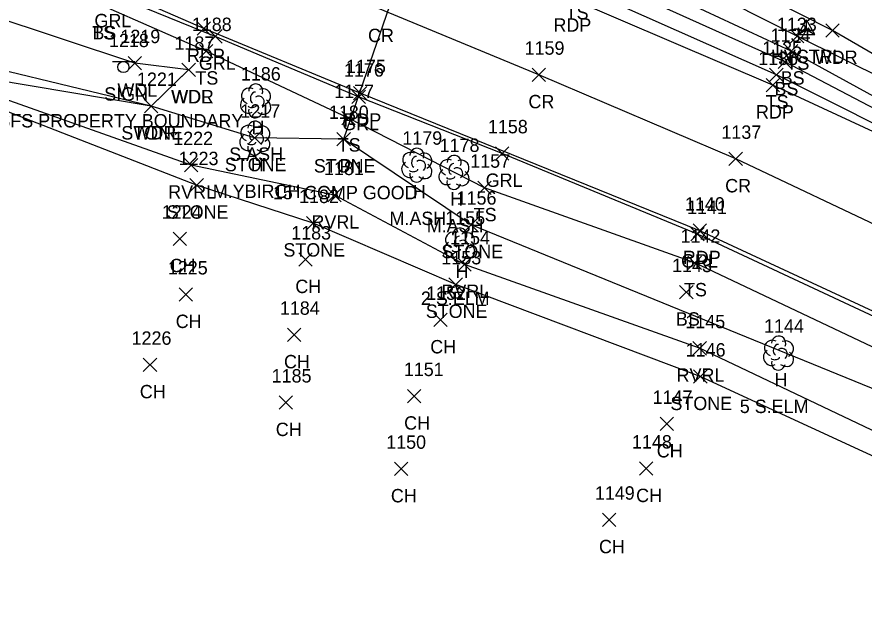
# Model space of a CAD drawing. Extents: x 1499292 to 1501024, y 534584 to 538043.
# Drawn here: x 1499970.1 to 1500096.6, y 537400.3 to 537488 of the extents above; entities that cross this region are included whole.
import ezdxf

# ---------------------------------------------------------------- set-up
doc = ezdxf.new("R2010")
doc.units = 0
for name, color, linetype in [('C_A', 7, 'Continuous'), ('CPSM', 7, 'Continuous'), ('D_A', 7, 'Continuous'), ('D_C', 7, 'Continuous'), ('D_I', 7, 'Continuous'), ('D_TIC', 7, 'Continuous'), ('DCP', 7, 'Continuous'), ('L_A', 7, 'Continuous'), ('L_C', 7, 'Continuous'), ('L_I', 7, 'Continuous'), ('L_TIC', 7, 'Continuous'), ('LASF', 7, 'Continuous'), ('LAWA', 7, 'Continuous'), ('LAWE', 7, 'Continuous'), ('LELB', 7, 'Continuous'), ('LTD', 7, 'Continuous'), ('P_A', 7, 'Continuous'), ('P_I', 7, 'Continuous'), ('P_TIC', 7, 'Continuous'), ('PET', 7, 'Continuous'), ('PRC', 7, 'Continuous'), ('R_A', 7, 'Continuous'), ('R_I', 7, 'Continuous'), ('R_TIC', 7, 'Continuous'), ('RGR', 7, 'Continuous'), ('S_A', 7, 'Continuous'), ('S_C', 7, 'Continuous'), ('S_I', 7, 'Continuous'), ('SSGN', 7, 'Continuous')]:
    doc.layers.add(name, color=color, linetype=linetype)

msp = doc.modelspace()

# ---------------------------------------------------------------- linework, layer by layer
at = {"layer": 'CPSM'}
for p, q in [((1500086.72, 537485.43), (1500087.97, 537487.6)), ((1500089.22, 537485.43), (1500087.97, 537487.6)), ((1500087.97, 537486.15), (1500087.97, 537487.6)), ((1500086.72, 537485.43), (1500087.97, 537486.15)), ((1500087.97, 537486.15), (1500087.97, 537486.15)), ((1500087.97, 537486.15), (1500089.22, 537485.43)), ((1500086.72, 537485.43), (1500089.22, 537485.43))]:
    msp.add_line(p, q, dxfattribs=at)
at = {"layer": 'D_TIC'}
for points in [[(1500017.89, 537468.8), (1500019.89, 537470.8)], [(1500019.89, 537468.8), (1500017.89, 537470.8)]]:
    msp.add_lwpolyline(points, dxfattribs=at)
at = {"layer": 'DCP'}
msp.add_lwpolyline([(1500032.11, 537508.21), (1500018.89, 537469.8)], dxfattribs=at)
at = {"layer": 'L_TIC'}
for points in [[(1500090.85, 537485.02), (1500092.85, 537487.02)], [(1500092.85, 537485.02), (1500090.85, 537487.02)], [(1500085.58, 537484.15), (1500087.58, 537486.15)], [(1500087.58, 537484.15), (1500085.58, 537486.15)], [(1499997.36, 537481.93), (1499999.36, 537483.93)], [(1499999.36, 537481.93), (1499997.36, 537483.93)], [(1500084.68, 537481.93), (1500086.68, 537483.93)], [(1500086.68, 537481.93), (1500084.68, 537483.93)], [(1499986.71, 537480.12), (1499988.71, 537482.12)], [(1499988.71, 537480.12), (1499986.71, 537482.12)], [(1500083.75, 537480.32), (1500085.75, 537482.32)], [(1500085.75, 537480.32), (1500083.75, 537482.32)], [(1499994.76, 537479.13), (1499996.76, 537481.13)], [(1499996.76, 537479.13), (1499994.76, 537481.13)], [(1499994.76, 537479.13), (1499996.76, 537481.13)], [(1499996.76, 537479.13), (1499994.76, 537481.13)], [(1500082.47, 537478.37), (1500084.47, 537480.37)], [(1500084.47, 537478.37), (1500082.47, 537480.37)], [(1499989.17, 537473.73), (1499991.17, 537475.73)], [(1499991.17, 537473.73), (1499989.17, 537475.73)], [(1499989.17, 537473.73), (1499991.17, 537475.73)], [(1499991.17, 537473.73), (1499989.17, 537475.73)], [(1500018.6, 537471.93), (1500020.6, 537473.93)], [(1500020.6, 537471.93), (1500018.6, 537473.93)], [(1500004.61, 537468.99), (1500006.61, 537470.99)], [(1500006.61, 537468.99), (1500004.61, 537470.99)], [(1500017.89, 537468.8), (1500019.89, 537470.8)], [(1500019.89, 537468.8), (1500017.89, 537470.8)], [(1499995.14, 537464.9), (1499997.14, 537466.9)], [(1499997.14, 537464.9), (1499995.14, 537466.9)], [(1499995.95, 537461.9), (1499997.95, 537463.9)], [(1499997.95, 537461.9), (1499995.95, 537463.9)], [(1500038.9, 537461.51), (1500040.9, 537463.51)], [(1500040.9, 537461.51), (1500038.9, 537463.51)], [(1500016.52, 537460.42), (1500018.52, 537462.42)], [(1500018.52, 537460.42), (1500016.52, 537462.42)], [(1500013.36, 537456.24), (1500015.36, 537458.24)], [(1500015.36, 537456.24), (1500013.36, 537458.24)], [(1500036.94, 537456), (1500038.94, 537458)], [(1500038.94, 537456), (1500036.94, 537458)], [(1499993.45, 537453.91), (1499995.45, 537455.91)], [(1499995.45, 537453.91), (1499993.45, 537455.91)], [(1500012.19, 537450.79), (1500014.19, 537452.79)], [(1500014.19, 537450.79), (1500012.19, 537452.79)], [(1500035.91, 537450.06), (1500037.91, 537452.06)], [(1500037.91, 537450.06), (1500035.91, 537452.06)], [(1500070.28, 537450.3), (1500072.28, 537452.3)], [(1500072.28, 537450.3), (1500070.28, 537452.3)], [(1500034.61, 537447.08), (1500036.61, 537449.08)], [(1500036.61, 537447.08), (1500034.61, 537449.08)], [(1500069.03, 537445.92), (1500071.03, 537447.92)], [(1500071.03, 537445.92), (1500069.03, 537447.92)], [(1499994.34, 537445.57), (1499996.34, 537447.57)], [(1499996.34, 537445.57), (1499994.34, 537447.57)], [(1500032.33, 537441.78), (1500034.33, 537443.78)], [(1500034.33, 537441.78), (1500032.33, 537443.78)], [(1500010.5, 537439.55), (1500012.5, 537441.55)], [(1500012.5, 537439.55), (1500010.5, 537441.55)], [(1500071.02, 537437.54), (1500073.02, 537439.54)], [(1500073.02, 537437.54), (1500071.02, 537439.54)], [(1499988.99, 537435.07), (1499990.99, 537437.07)], [(1499990.99, 537435.07), (1499988.99, 537437.07)], [(1500071.12, 537433.31), (1500073.12, 537435.31)], [(1500073.12, 537433.31), (1500071.12, 537435.31)], [(1500009.27, 537429.43), (1500011.27, 537431.43)], [(1500011.27, 537429.43), (1500009.27, 537431.43)], [(1500028.43, 537430.39), (1500030.43, 537432.39)], [(1500030.43, 537430.39), (1500028.43, 537432.39)], [(1500066.13, 537426.24), (1500068.13, 537428.24)], [(1500068.13, 537426.24), (1500066.13, 537428.24)], [(1500026.46, 537419.53), (1500028.46, 537421.53)], [(1500028.46, 537419.53), (1500026.46, 537421.53)], [(1500063.05, 537419.57), (1500065.05, 537421.57)], [(1500065.05, 537419.57), (1500063.05, 537421.57)], [(1500057.52, 537411.93), (1500059.52, 537413.93)], [(1500059.52, 537411.93), (1500057.52, 537413.93)]]:
    msp.add_lwpolyline(points, dxfattribs=at)
at = {"layer": 'LASF'}
for points in [[(1500267.15, 537320.21), (1500231.86, 537353.04), (1500206.49, 537372.95), (1500185.23, 537386.26), (1500150.04, 537409.52), (1500131.44, 537420.15), (1500124.35, 537420.07), (1500118.75, 537423.95), (1500037.94, 537457), (1500018.89, 537469.8), (1500005.61, 537469.99), (1499990.17, 537474.73), (1499954.28, 537480.72)], [(1500257.29, 537311.49), (1500228.04, 537343.24), (1500201.61, 537364.07), (1500181.84, 537376.06), (1500148.43, 537396.84), (1500112.98, 537415.44), (1500072.12, 537434.31), (1500035.61, 537448.08), (1500014.36, 537457.24), (1499996.95, 537462.9), (1499955.82, 537478.87)]]:
    msp.add_lwpolyline(points, dxfattribs=at)
at = {"layer": 'LAWA'}
for points in [[(1499995.76, 537480.13), (1499987.71, 537481.12), (1499965.63, 537488.45), (1499951.19, 537496.8), (1499940.31, 537506.49), (1499921.73, 537516.37), (1499909.85, 537530.28), (1499895.31, 537551.67), (1499880.56, 537573.45), (1499869.59, 537586.01)], [(1500296.25, 537345.3), (1500256.73, 537378.82), (1500246.41, 537388.79), (1500239.52, 537392.77), (1500228.03, 537398.5), (1500203.66, 537420.68), (1500174.13, 537441.21), (1500133.61, 537461.8), (1500091.85, 537486.02), (1500057.95, 537503.18), (1500037.17, 537516.58), (1500027.18, 537529.7), (1500016.43, 537544.22), (1500024.22, 537554.38), (1500031.9, 537568.77)], [(1499995.76, 537480.13), (1499990.17, 537474.73), (1499955.16, 537483.15), (1499929.82, 537484.96), (1499907.75, 537492.08), (1499888.5, 537505.17), (1499866.75, 537513.41), (1499844.02, 537524.83), (1499812.32, 537544.37), (1499782.43, 537547.26), (1499779.42, 537543.38), (1499776.68, 537541.14), (1499771.06, 537541.38)]]:
    msp.add_lwpolyline(points, dxfattribs=at)
at = {"layer": 'LAWE'}
msp.add_lwpolyline([(1500261.99, 537313.66), (1500228.82, 537347.03), (1500202.26, 537367.71), (1500183.69, 537379.24), (1500148.94, 537399.95), (1500115.08, 537418.07), (1500072.02, 537438.54), (1500036.91, 537451.06), (1500017.52, 537461.42), (1499996.14, 537465.9), (1499954.28, 537480.72), (1499927.31, 537482.22), (1499904.29, 537486.53), (1499884.65, 537502.32), (1499865.55, 537506.45), (1499842.14, 537517.49), (1499811.08, 537534.65), (1499790.47, 537534.56), (1499747.78, 537525.03), (1499698.85, 537529.6)], dxfattribs=at)
at = {"layer": 'LELB'}
for points in [[(1500290.71, 537339.51), (1500254.04, 537373.68), (1500224.98, 537395.42), (1500200.73, 537412.86), (1500170.41, 537433.92), (1500131.37, 537455.4), (1500083.47, 537479.37), (1500053.62, 537492.68), (1500030.68, 537505.22), (1500012.53, 537513.88), (1499991.95, 537522.3), (1499974.49, 537532.11), (1499955.61, 537546.28), (1499937.72, 537561.94), (1499940.61, 537580.36), (1499943.98, 537590.51), (1499964.26, 537598.71), (1499981.02, 537608.13), (1500000.32, 537612.94)], [(1500292.43, 537341.34), (1500255.06, 537375.07), (1500226.32, 537396.72), (1500201.26, 537414.48), (1500171.22, 537435.38), (1500132.04, 537457.48), (1500085.68, 537482.93), (1500055.74, 537496.91), (1500032.99, 537510.71), (1500014.29, 537519.36), (1499996.72, 537526.9), (1499977.93, 537538.66), (1499965.7, 537556.17), (1499963.9, 537570.61), (1499969.57, 537590.89), (1499978.12, 537601.79)], [(1500291.4, 537340.15), (1500254.56, 537374.3), (1500225.71, 537395.92), (1500201.33, 537413.51), (1500170.9, 537434.45), (1500131.84, 537456.62), (1500084.75, 537481.32), (1500054.37, 537495.03), (1500032.11, 537508.21), (1500014.29, 537516), (1499993.85, 537524.95), (1499976.65, 537535.86), (1499959.1, 537549.21), (1499939.76, 537563.39), (1499940.61, 537580.36)], [(1500294.64, 537343.13), (1500255.06, 537375.07), (1500255.51, 537377.72), (1500228.03, 537398.5), (1500201.95, 537416.01), (1500172.91, 537436.91), (1500133.61, 537461.8), (1500086.58, 537485.15), (1500056.84, 537500.25), (1500033.98, 537513.25), (1500019.27, 537523.87)], [(1500131.44, 537420.15), (1500118.57, 537428.9), (1500071.28, 537451.3), (1500039.9, 537462.51), (1500019.6, 537472.93), (1499998.36, 537482.93), (1499982.95, 537489.68), (1499968.67, 537496.83), (1499953.48, 537503.61), (1499943.52, 537510.2)]]:
    msp.add_lwpolyline(points, dxfattribs=at)
at = {"layer": 'LTD'}
for p, q in [((1500005.73, 537475.54), (1500005.73, 537475.54)), ((1500005.73, 537475.54), (1500005.73, 537475.54)), ((1500005.61, 537469.99), (1500005.61, 537469.99)), ((1500005.61, 537469.99), (1500005.61, 537469.99)), ((1500029.79, 537465.95), (1500029.79, 537465.95)), ((1500029.79, 537465.95), (1500029.79, 537465.95)), ((1500035.34, 537464.87), (1500035.34, 537464.87)), ((1500035.34, 537464.87), (1500035.34, 537464.87)), ((1500036.18, 537454.02), (1500036.18, 537454.02)), ((1500036.18, 537454.02), (1500036.18, 537454.02)), ((1500083.77, 537437.87), (1500083.77, 537437.87)), ((1500083.77, 537437.87), (1500083.77, 537437.87))]:
    msp.add_line(p, q, dxfattribs=at)
for centre in [(1500005.77, 537476.98), (1500005.66, 537471.42), (1500029.83, 537467.38), (1500035.39, 537466.3), (1500036.23, 537455.46), (1500083.82, 537439.31)]:
    msp.add_arc(centre, 1.05, 335.5272, 180.9563, dxfattribs=at)
for centre, major_axis, ratio, start_param, end_param in [((1500004.94, 537476.21), (1.21, -0.51), 0.895232, 1.570796, 4.712389), ((1500005.52, 537476), (-0.208, -0.792), 0.645439, 3.141593, 6.283185), ((1500006.77, 537476.13), (-1.14, -0.48), 0.949671, 1.570796, 4.712389), ((1500004.64, 537474.84), (0.58, -1.04), 0.959034, 3.141593, 6.283185), ((1500006.23, 537475.38), (-0.5, 0.667), 0.989748, 3.141593, 6.283185), ((1500006.73, 537474.71), (-1.09, 0.79), 0.841452, 1.570796, 4.712389), ((1500005.73, 537474.04), (0.26, 1.06), 0.942809, 1.570796, 4.712389), ((1500005.27, 537474.79), (-0.625, -0.083), 0.423636, 0, 3.141593), ((1500004.82, 537470.66), (1.21, -0.51), 0.895232, 1.570796, 4.712389), ((1500006.65, 537470.57), (-1.14, -0.48), 0.949671, 1.570796, 4.712389), ((1500005.4, 537470.45), (-0.208, -0.792), 0.645439, 3.141593, 6.283185), ((1500006.11, 537469.82), (-0.5, 0.667), 0.989748, 3.141593, 6.283185), ((1500004.53, 537469.28), (0.58, -1.04), 0.959034, 3.141593, 6.283185), ((1500005.15, 537469.24), (-0.625, -0.083), 0.423636, 0, 3.141593), ((1500006.61, 537469.16), (-1.09, 0.79), 0.841452, 1.570796, 4.712389), ((1500005.61, 537468.49), (0.26, 1.06), 0.942809, 1.570796, 4.712389), ((1500028.99, 537466.61), (1.21, -0.51), 0.895232, 1.570796, 4.712389), ((1500029.58, 537466.4), (-0.208, -0.792), 0.645439, 3.141593, 6.283185), ((1500030.29, 537465.78), (-0.5, 0.667), 0.989748, 3.141593, 6.283185), ((1500030.83, 537466.53), (-1.14, -0.48), 0.949671, 1.570796, 4.712389), ((1500034.55, 537465.54), (1.21, -0.51), 0.895232, 1.570796, 4.712389), ((1500036.38, 537465.45), (-1.14, -0.48), 0.949671, 1.570796, 4.712389), ((1500028.7, 537465.24), (0.58, -1.04), 0.959034, 3.141593, 6.283185), ((1500030.79, 537465.11), (-1.09, 0.79), 0.841452, 1.570796, 4.712389), ((1500035.13, 537465.33), (-0.208, -0.792), 0.645439, 3.141593, 6.283185), ((1500035.84, 537464.7), (-0.5, 0.667), 0.989748, 3.141593, 6.283185), ((1500029.79, 537464.45), (0.26, 1.06), 0.942809, 1.570796, 4.712389), ((1500029.33, 537465.2), (-0.625, -0.083), 0.423636, 0, 3.141593), ((1500034.26, 537464.16), (0.58, -1.04), 0.959034, 3.141593, 6.283185), ((1500034.88, 537464.12), (-0.625, -0.083), 0.423636, 0, 3.141593), ((1500036.34, 537464.04), (-1.09, 0.79), 0.841452, 1.570796, 4.712389), ((1500035.34, 537463.37), (0.26, 1.06), 0.942809, 1.570796, 4.712389), ((1500035.39, 537454.69), (1.21, -0.51), 0.895232, 1.570796, 4.712389), ((1500035.97, 537454.48), (-0.208, -0.792), 0.645439, 3.141593, 6.283185), ((1500037.22, 537454.61), (-1.14, -0.48), 0.949671, 1.570796, 4.712389), ((1500035.1, 537453.31), (0.58, -1.04), 0.959034, 3.141593, 6.283185), ((1500036.68, 537453.86), (-0.5, 0.667), 0.989748, 3.141593, 6.283185), ((1500037.18, 537453.19), (-1.09, 0.79), 0.841452, 1.570796, 4.712389), ((1500036.18, 537452.52), (0.26, 1.06), 0.942809, 1.570796, 4.712389), ((1500035.72, 537453.27), (-0.625, -0.083), 0.423636, 0, 3.141593), ((1500082.98, 537438.54), (1.21, -0.51), 0.895232, 1.570796, 4.712389), ((1500083.56, 537438.33), (-0.208, -0.792), 0.645439, 3.141593, 6.283185), ((1500084.81, 537438.46), (-1.14, -0.48), 0.949671, 1.570796, 4.712389), ((1500082.69, 537437.17), (0.58, -1.04), 0.959034, 3.141593, 6.283185), ((1500084.27, 537437.71), (-0.5, 0.667), 0.989748, 3.141593, 6.283185), ((1500084.77, 537437.04), (-1.09, 0.79), 0.841452, 1.570796, 4.712389), ((1500083.77, 537436.37), (0.26, 1.06), 0.942809, 1.570796, 4.712389), ((1500083.31, 537437.12), (-0.625, -0.083), 0.423636, 0, 3.141593)]:
    msp.add_ellipse(centre, major_axis=major_axis, ratio=ratio, start_param=start_param, end_param=end_param, dxfattribs=at)
at = {"layer": 'P_TIC'}
for points in [[(1499997.02, 537485.29), (1499999.02, 537487.29)], [(1499999.02, 537485.29), (1499997.02, 537487.29)], [(1500047.03, 537478.39), (1500049.03, 537480.39)], [(1500049.03, 537478.39), (1500047.03, 537480.39)], [(1500081.94, 537476.86), (1500083.94, 537478.86)], [(1500083.94, 537476.86), (1500081.94, 537478.86)], [(1500020.37, 537475.64), (1500022.37, 537477.64)], [(1500022.37, 537475.64), (1500020.37, 537477.64)], [(1500076.4, 537465.83), (1500078.4, 537467.83)], [(1500078.4, 537465.83), (1500076.4, 537467.83)], [(1500071.03, 537455.11), (1500073.03, 537457.11)], [(1500073.03, 537455.11), (1500071.03, 537457.11)]]:
    msp.add_lwpolyline(points, dxfattribs=at)
at = {"layer": 'PET'}
for points in [[(1500289.78, 537338.29), (1500253.04, 537372.98), (1500224.75, 537395.04), (1500200.64, 537412.65), (1500169.79, 537433.28), (1500131.37, 537455.4), (1500082.94, 537477.86), (1500052.71, 537490.83), (1500028.69, 537501.08), (1500007.59, 537509.93), (1499989.8, 537518.65), (1499972.48, 537528.52), (1499952.08, 537542.88), (1499935.46, 537557.31), (1499909.99, 537586.35), (1499888.96, 537613.55)], [(1500270.13, 537322.4), (1500238.22, 537353.72), (1500209.42, 537377.09), (1500189.13, 537391.85), (1500154.51, 537414.13), (1500120.36, 537433.62), (1500072.03, 537456.11), (1500021.37, 537476.64), (1499998.02, 537486.29), (1499978.14, 537495.01), (1499958.62, 537505.35), (1499935.09, 537521.93), (1499915.79, 537539.45), (1499898.17, 537558.63), (1499884.72, 537577.02)]]:
    msp.add_lwpolyline(points, dxfattribs=at)
at = {"layer": 'PRC'}
msp.add_lwpolyline([(1500278.96, 537330.13), (1500245.16, 537363.32), (1500217.07, 537386.35), (1500194.78, 537402.07), (1500161.59, 537424.07), (1500124.89, 537444.32), (1500077.4, 537466.83), (1500048.03, 537479.39), (1500024.1, 537489.28), (1500002.86, 537498.23), (1499984.27, 537507.12), (1499965.54, 537516.89), (1499943.1, 537532.26), (1499924.7, 537548.4), (1499906.7, 537567.9), (1499892.97, 537586.05), (1499884.57, 537597.67), (1499868.24, 537621.71), (1499849.2, 537650.1), (1499837.66, 537665.34), (1499832.02, 537672.42)], dxfattribs=at)
at = {"layer": 'R_TIC'}
for points in [[(1499998.74, 537484.14), (1500000.74, 537486.14)], [(1500000.74, 537484.14), (1499998.74, 537486.14)], [(1500020.13, 537475.12), (1500022.13, 537477.12)], [(1500022.13, 537475.12), (1500020.13, 537477.12)], [(1500041.55, 537466.65), (1500043.55, 537468.65)], [(1500043.55, 537466.65), (1500041.55, 537468.65)], [(1500070.71, 537454.6), (1500072.71, 537456.6)], [(1500072.71, 537454.6), (1500070.71, 537456.6)]]:
    msp.add_lwpolyline(points, dxfattribs=at)
at = {"layer": 'RGR'}
msp.add_lwpolyline([(1500269.09, 537321.92), (1500237.75, 537353.24), (1500209.1, 537376.73), (1500188.83, 537391.14), (1500154.15, 537413.64), (1500120.04, 537433), (1500071.71, 537455.6), (1500042.55, 537467.65), (1500021.13, 537476.12), (1499999.74, 537485.14), (1499984.16, 537491.49), (1499962.3, 537501.56), (1499943.52, 537510.2), (1499936.88, 537512.97), (1499926.59, 537517.73)], dxfattribs=at)
at = {"layer": 'SSGN'}
for p, q in [((1499984.37, 537481.39), (1499987.71, 537481.39)), ((1499986.02, 537480.55), (1499986.02, 537480.55))]:
    msp.add_line(p, q, dxfattribs=at)
msp.add_circle((1499986.02, 537480.55), 0.833, dxfattribs=at)

# ---------------------------------------------------------------- texts
at = {"layer": 'C_A'}
msp.add_text('HVCTRL', height=2, dxfattribs=at).set_placement((1500082.66, 537481.15))
at = {"layer": 'D_A'}
msp.add_text('P', height=2, dxfattribs=at).set_placement((1500018.27, 537464.8))
at = {"layer": 'D_C'}
msp.add_text('15" CGMP GOOD', height=2, dxfattribs=at).set_placement((1500008.32, 537460.8))
at = {"layer": 'D_I'}
msp.add_text('1180', height=2, dxfattribs=at).set_placement((1500016.68, 537472.8))
at = {"layer": 'L_A'}
for s, p in [('TS', (1500052.03, 537487.68)), ('TS', (1499981.36, 537484.68)), ('BS', (1499981.39, 537484.68)), ('TS', (1500084.98, 537480.15)), ('WDR', (1500089.21, 537481.02)), ('TS', (1499996.77, 537477.93)), ('BS', (1500084.12, 537477.93)), ('WDL', (1499985.13, 537476.12)), ('BS', (1500083.19, 537476.32)), ('WDR', (1499993.13, 537475.13)), ('WDL', (1499993.18, 537475.13)), ('TS', (1500081.88, 537474.37)), ('STONE', (1499985.71, 537469.73)), ('H', (1500005.16, 537470.54)), ('WDR', (1499987.53, 537469.73)), ('TS', (1500018.01, 537467.93)), ('STONE', (1500001.15, 537464.99)), ('H', (1500005.04, 537464.99)), ('STONE', (1500014.44, 537464.8)), ('RVRL', (1499992.71, 537460.9)), ('H', (1500029.22, 537460.95)), ('H', (1500034.77, 537459.87)), ('STONE', (1499992.49, 537457.9)), ('TS', (1500038.31, 537457.51)), ('RVRL', (1500014.09, 537456.42)), ('STONE', (1500009.9, 537452.24)), ('STONE', (1500033.48, 537452)), ('CH', (1499992.93, 537449.91)), ('H', (1500035.61, 537449.02)), ('CH', (1500011.68, 537446.79)), ('RVRL', (1500033.48, 537446.06)), ('TS', (1500069.69, 537446.3)), ('STONE', (1500031.15, 537443.08)), ('BS', (1500068.47, 537441.92)), ('CH', (1499993.83, 537441.57)), ('CH', (1500031.82, 537437.78)), ('CH', (1500009.99, 537435.55)), ('RVRL', (1500068.58, 537433.54)), ('H', (1500083.2, 537432.87)), ('CH', (1499988.47, 537431.07)), ('STONE', (1500067.66, 537429.31)), ('CH', (1500027.92, 537426.39)), ('CH', (1500008.76, 537425.43)), ('CH', (1500065.62, 537422.24)), ('CH', (1500025.94, 537415.53)), ('CH', (1500062.54, 537415.57)), ('CH', (1500057, 537407.93))]:
    msp.add_text(s, height=2, dxfattribs=at).set_placement(p)
at = {"layer": 'L_C'}
for s, p in [('S.ASH', (1500001.81, 537466.54)), ('M.YBIRCH', (1499999.36, 537460.99)), ('M.ASH', (1500025.74, 537456.95)), ('M.ASH', (1500031.29, 537455.87)), ('2 S.ELM', (1500030.42, 537445.02)), ('5 S.ELM', (1500078.01, 537428.87))]:
    msp.add_text(s, height=2, dxfattribs=at).set_placement(p)
at = {"layer": 'L_I'}
for s, p in [('1188', (1499996.23, 537485.93)), ('1133', (1500083.55, 537485.93)), ('1219', (1499985.57, 537484.12)), ('1134', (1500082.62, 537484.32)), ('1187', (1499993.64, 537483.13)), ('1187', (1499993.64, 537483.13)), ('1135', (1500081.35, 537482.37)), ('1221', (1499988.05, 537477.73)), ('1221', (1499988.05, 537477.73)), ('1186', (1500003.55, 537478.54)), ('1177', (1500017.48, 537475.93)), ('1217', (1500003.48, 537472.99)), ('1217', (1500003.48, 537472.99)), ('1180', (1500016.68, 537472.8)), ('1222', (1499993.45, 537468.9)), ('1179', (1500027.65, 537468.95)), ('1178', (1500033.21, 537467.87)), ('1223', (1499994.26, 537465.9)), ('1157', (1500037.78, 537465.51)), ('1181', (1500015.96, 537464.42)), ('1182', (1500012.24, 537460.24)), ('1156', (1500035.75, 537460)), ('1224', (1499991.75, 537457.91)), ('1155', (1500034.05, 537457.02)), ('1183', (1500011.06, 537454.79)), ('1154', (1500034.78, 537454.06)), ('1142', (1500069.16, 537454.3)), ('1153', (1500033.48, 537451.08)), ('1225', (1499992.65, 537449.57)), ('1143', (1500067.91, 537449.92)), ('1152', (1500031.2, 537445.78)), ('1184', (1500009.37, 537443.55)), ('1145', (1500069.89, 537441.54)), ('1144', (1500081.64, 537440.87)), ('1226', (1499987.24, 537439.07)), ('1146', (1500069.94, 537437.31)), ('1151', (1500027.87, 537434.39)), ('1185', (1500008.15, 537433.43)), ('1147', (1500065, 537430.24)), ('1150', (1500025.24, 537423.53)), ('1148', (1500061.92, 537423.57)), ('1149', (1500056.38, 537415.93))]:
    msp.add_text(s, height=2, dxfattribs=at).set_placement(p)
at = {"layer": 'P_A'}
for s, p in [('RDP', (1500050.2, 537485.83)), ('CR', (1500022.53, 537484.28)), ('RDP', (1499995.51, 537481.29)), ('CR', (1500046.47, 537474.39)), ('RDP', (1500080.43, 537472.86)), ('RDP', (1500018.86, 537471.64)), ('CR', (1500075.83, 537461.83)), ('RDP', (1500069.52, 537451.11))]:
    msp.add_text(s, height=2, dxfattribs=at).set_placement(p)
at = {"layer": 'P_I'}
for s, p in [('1159', (1500045.9, 537482.39)), ('1136', (1500080.76, 537480.86)), ('1175', (1500019.24, 537479.64)), ('1137', (1500075.27, 537469.83)), ('1140', (1500069.82, 537459.11))]:
    msp.add_text(s, height=2, dxfattribs=at).set_placement(p)
at = {"layer": 'R_A'}
for p in [(1499981.7, 537486.49), (1499997.28, 537480.14), (1500018.67, 537471.12), (1500040.09, 537462.65), (1500069.25, 537450.6)]:
    msp.add_text('GRL', height=2, dxfattribs=at).set_placement(p)
at = {"layer": 'R_I'}
for s, p in [('1176', (1500018.94, 537479.12)), ('1158', (1500040.42, 537470.65)), ('1141', (1500070.15, 537458.6))]:
    msp.add_text(s, height=2, dxfattribs=at).set_placement(p)
at = {"layer": 'S_A'}
msp.add_text('SIGN', height=2, dxfattribs=at).set_placement((1499983.16, 537475.53))
at = {"layer": 'S_C'}
msp.add_text('USFS PROPERTY BOUNDARY', height=2, dxfattribs=at).set_placement((1499965.43, 537471.53))
at = {"layer": 'S_I'}
msp.add_text('1218', height=2, dxfattribs=at).set_placement((1499983.87, 537483.53))

doc.saveas('drawing.dxf')
